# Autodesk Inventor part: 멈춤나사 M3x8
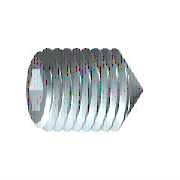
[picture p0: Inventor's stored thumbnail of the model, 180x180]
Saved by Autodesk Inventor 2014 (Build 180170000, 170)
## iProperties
Created: 2012-02
Part Number: 멈춤나사 M3x8
Material: 강철, 연강
Description: 6각 소켓 머리 없는 멈춤 나사
Document SubType Name: Modeling
Standard: KS B 1028
Designer: mduedu
Standards Organization: KS
Language: ko-KR
Size Designation: 원추점 M3x8
Categories: <MemberInstance><Categories><Category DisplayName="조임쇠" InternalName="e4da775c-781d-43d5-af7c-5136215cf5a6" Mnemonic="FSTN"><Category DisplayName="볼트" InternalN
Density: 7.86 g/cm^3
Mass: 0.360339 g
Surface Area: 0.888172 cm^2
Volume: 0.0458447 cm^3
Appearance: 강철
IsCustomPart: 1
Author: mduedu
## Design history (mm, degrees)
sketch "스케치1"
  geometry: L1 (0, 0)-(5.5, 0); L2 (8, 0.866)-(8, 1.5); L3 (8, 1.5)-(0, 1.5); L4 (8, 0.866)-(6, 0.866); L5 (6, 0.866)-(5.5, 0); L6 (0, -0.3)-(0, 1.8) reference; L7 (0, 1.5)-(0, 0)
  constraints: 13 end point, 3 parallel, 1 collinear, 1 perpendicular, 1 point on line
  dimensions: "d0" = 2 distance of L2.start L4.end (= INTI); "d1" = 60 deg angle of L5 L1; "d2" = 3 diameter of L3 L1 (= NND); "d3" = 1.73205 diameter of L4 L1 (= 1.1547 x SW); "d5" = 8 distance from line of L2 L3.end (= NLG)
revolve "본체" sketch "스케치1" stored, may be unused: angle "d6" = 90 deg
sketch "스케치2"
  geometry: L1 (-0.433, 0.75)-(0.433, 0.75); L2 (0.433, 0.75)-(0.866, 0); L3 (0.866, 0)-(0.433, -0.75); L4 (0.433, -0.75)-(-0.433, -0.75); L5 (-0.433, -0.75)-(-0.866, 0); L6 (-0.866, 0)-(-0.433, 0.75); 3 further points
  constraints: 12 end point, 1 coincident, 1 horizontal, 13 other
extrude "슬롯" join sketch "스케치2" taper "d7" = 0 deg; stored distance "d21" = 10
workaxis "Work Axis1"
workplane "Work Plane1"
sketch "스케치5"
  geometry: L1 (-4, -0.15)-(-2.65, -1.5) reference; L2 (-4, 0.15)-(-2.65, 1.5) reference; L3 (-2.65, 1.5)-(-4.15, 0); L4 (-2.65, -1.5)-(-4.15, 0); 1 further point
  constraints: 4 end point, 1 horizontal alignment, 1 perpendicular
node "작업점1"
body "Solid1"
feature "스레드" dims "d12" = 8 (= NLG), "d13" = 0
chamfer "모따기1" distance "d8" = 1.35 (computed from NND, SPD, FAWI); stored, may be unused: angle "d9" = 45 deg (= FAWI), second distance "d34" = 1.35 (computed from NND, SPD, FAWI)
chamfer "모따기2" distance "d10" = 0.30673 (= -0.5 x GD1 + 0.5 x NND); stored, may be unused: angle "d11" = 45 deg (= FAWI), second distance "d35" = 0.30673 (= -0.5 x GD1 + 0.5 x NND)
other parameters: "NND" = 3 [user parameter; used in 5 equation terms], "NLG" = 8 [user parameter; used in 2 equation terms], "INTI" = 2 [user parameter; used in 1 equation term], "FAWI" = 45 deg [user parameter; used in 4 equation terms], "SW" = 1.5 [user parameter; used in 2 equation terms], "GD1" = 2.38655 (= THREADDIA - 1.2269 x PTC) [user parameter; used in 2 equation terms], "d4" = 0, "FAWI1" = 45 deg [user parameter], "SPD" = 0.3 [user parameter; used in 2 equation terms], "d36" = 0, "d37" = 0, "GUL" = 0.30673 (= 0.61345 x PTC) [user parameter], "TOA" = 30 deg [user parameter], "THREADDIA" = 3 [user parameter; used in 1 equation term], "PTC" = 0.5 [user parameter; used in 4 equation terms], "GAL" = 0.30673 (= 0.61345 x PTC) [user parameter], "E0" = 1.7325 (= 1.155 x SW) [user parameter]
